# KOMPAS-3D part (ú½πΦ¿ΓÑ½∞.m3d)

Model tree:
1. Эскиз:1
2. Операция выдавливания:1
     Расстояние 1 = 10; Расстояние 2 = 4.9
3. Эскиз:2
4. Вырезать элемент выдавливания:1
     Расстояние 1 = 30.0766
5. Эскиз:3
6. Операция выдавливания:2
     Расстояние 1 = 1; Расстояние 2 = 4.9
7. Эскиз:4
8. Вырезать элемент выдавливания:2
     Расстояние 1 = 7.5
9. Скругление:1
     Радиус = 1
10. Эскиз:6
11. Операция выдавливания:3
     Расстояние 1 = 1; Расстояние 2 = 4.9
12. Эскиз:7
13. Операция выдавливания:4
     Расстояние 1 = 11
14. Эскиз:8
15. Вырезать элемент выдавливания:3
     Расстояние 1 = 0.6
16. Эскиз:9
17. Вырезать элемент выдавливания:4
     Расстояние 1 = 0.6
18. Скругление:2
     Радиус = 1
19. Эскиз:10
20. Операция выдавливания:5
     Расстояние 1 = 11
21. Эскиз:11
22. Вырезать элемент выдавливания:5
     Расстояние 1 = 0.6
23. Эскиз:12
24. Вырезать элемент выдавливания:6
     Расстояние 1 = 0.6
25. Скругление:3
     Радиус = 1
26. Эскиз:13
27. Операция выдавливания:6
     Расстояние 1 = 4; Расстояние 2 = 0.5
28. Эскиз:14
29. Операция выдавливания:7
     Расстояние 1 = 1; Расстояние 2 = 0.5
30. Эскиз:15
31. Вырезать элемент выдавливания:7
     Расстояние 1 = 29.9213
32. Эскиз:16
33. Операция выдавливания:8
     Расстояние 1 = 1; Расстояние 2 = 0.5
34. Скругление:4
     Радиус = 1
35. Скругление:5
     Радиус = 1
36. Эскиз:17
37. Операция выдавливания:9
     Расстояние 1 = 0.5; Расстояние 2 = 2
38. Скругление:7
     Радиус = 0.5
39. Эскиз:18
40. Операция выдавливания:10
     Расстояние 1 = 0.5; Расстояние 2 = 2
41. Скругление:8
     Радиус = 0.5
42. Эскиз:19
43. Операция выдавливания:11
     Расстояние 1 = 0.5; Расстояние 2 = 2
44. Эскиз:20
45. Вырезать элемент выдавливания:8
     Расстояние 1 = 5
46. Эскиз:21
47. Операция выдавливания:12
     Расстояние 1 = 0.5; Угол 1 = 11; Расстояние 2 = 2
48. Скругление:9
     Радиус = 0.5
49. Скругление:10
     Радиус = 0.5
50. Скругление:11
     Радиус = 0.5
51. Скругление:13
     Радиус = 0.5
52. Эскиз:22
53. Вырезать элемент выдавливания:9
     Расстояние 1 = 33.7844
54. Скругление:14
     Радиус = 0.5

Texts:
  Сплав АЛ8  ГОСТ 1583-93
  stalker61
